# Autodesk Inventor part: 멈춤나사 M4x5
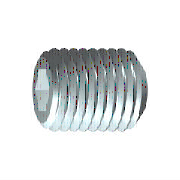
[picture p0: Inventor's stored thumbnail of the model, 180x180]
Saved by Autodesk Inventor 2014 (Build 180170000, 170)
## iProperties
IsCustomPart: 1
Created: 2012-02
Part Number: 멈춤나사 M4x5
Material: 강철, 연강
Description: 6각 소켓 머리 없는 멈춤 나사
Document SubType Name: Modeling
Standard: KS B 1028
Designer: mduedu
Standards Organization: KS
Language: ko-KR
Size Designation: 납작점M4x5
Categories: <MemberInstance><Categories><Category DisplayName="조임쇠" InternalName="e4da775c-781d-43d5-af7c-5136215cf5a6" Mnemonic="FSTN"><Category DisplayName="볼트" InternalN
Density: 7.86 g/cm^3
Appearance: 노란색
Mass: 0.401763 g
Surface Area: 0.994256 cm^2
Volume: 0.0511149 cm^3
Author: mduedu
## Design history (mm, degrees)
sketch "스케치1"
  geometry: L1 (0, 0)-(1.833, 0); L2 (5, 1.155)-(5, 2); L3 (5, 2)-(0, 2); L4 (5, 1.155)-(2.5, 1.155); L5 (2.5, 1.155)-(1.833, 0); L6 (0, -0.4)-(0, 2.4) reference; L7 (0, 2)-(0, 0)
  constraints: 13 end point, 3 parallel, 1 collinear, 1 perpendicular, 1 point on line
  dimensions: "d0" = 2.5 distance of L2.start L4.end (= INTI); "d1" = 60 deg angle of L5 L1; "d2" = 4 diameter of L3 L1 (= NND); "d3" = 2.3094 diameter of L4 L1 (= 1.1547 x SW); "d5" = 5 distance from line of L2 L3.end (= NLG)
revolve "본체" sketch "스케치1" stored, may be unused: angle "d6" = 90 deg
sketch "스케치2"
  geometry: L1 (-0.577, 1)-(0.577, 1); L2 (0.577, 1)-(1.155, 0); L3 (1.155, 0)-(0.577, -1); L4 (0.577, -1)-(-0.577, -1); L5 (-0.577, -1)-(-1.155, 0); L6 (-1.155, 0)-(-0.577, 1); A1 r 1.155 centre (0, 0) between (-0.577, 1) and (0.577, 1) reference; 2 further points
  constraints: 12 end point, 2 point on circle, 1 coincident, 1 horizontal, 11 other
extrude "슬롯" join sketch "스케치2" taper "d9" = 0 deg; stored distance "d21" = 10
workaxis "Work Axis1"
workplane "Work Plane1"
body "Solid1"
chamfer "모따기1" distance "d7" = 0.42941 (= -0.5 x GD1 + 0.5 x NND); stored, may be unused: angle "d8" = 45 deg (= FAWI), second distance "d29" = 0.42941 (= -0.5 x GD1 + 0.5 x NND)
feature "스레드" dims "d11" = 5 (= NLG), "d12" = 0
chamfer "모따기2" distance "d13" = 0.42941 (= -0.5 x GD1 + 0.5 x NND); stored, may be unused: angle "d14" = 45 deg (= FAWI), second distance "d30" = 0.42941 (= -0.5 x GD1 + 0.5 x NND)
other parameters: "NND" = 4 [user parameter; used in 5 equation terms], "NLG" = 5 [user parameter; used in 2 equation terms], "INTI" = 2.5 [user parameter; used in 1 equation term], "FAWI" = 45 deg [user parameter; used in 2 equation terms], "SW" = 2 [user parameter; used in 2 equation terms], "GD1" = 3.14117 (= THREADDIA - 1.2269 x PTC) [user parameter; used in 4 equation terms], "d4" = 0, "FAWI1" = 45 deg [user parameter], "d15" = 0, "d31" = 0, "GUL" = 0.42941 (= 0.61345 x PTC) [user parameter], "SPD" = 2.5 [user parameter], "TPU" = 14.28571 (computed from PTC) [user parameter], "TOA" = 30 deg [user parameter], "THREADDIA" = 4 [user parameter; used in 1 equation term], "PTC" = 0.7 [user parameter; used in 4 equation terms], "GAL" = 0.42941 (= 0.61345 x PTC) [user parameter], "E0" = 2.31 (= 1.155 x SW) [user parameter]
